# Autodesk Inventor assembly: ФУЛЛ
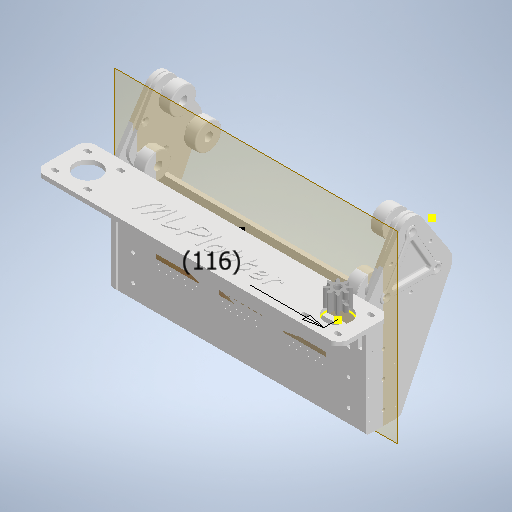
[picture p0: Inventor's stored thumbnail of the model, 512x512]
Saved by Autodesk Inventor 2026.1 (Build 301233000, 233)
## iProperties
Created: 2025-12
Part Number: ФУЛЛ
Document SubType Name: Assembly
Designer: Yury Melnikov
Author: Yury Melnikov
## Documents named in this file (8)
- C:\Users\user\Documents\Проекты\ВсОШ_РОБО\ФУЛЛ.iam
- C:\Users\user\Documents\Проекты\ВсОШ_РОБО\Стенд\СТЕНД.iam
- C:\Users\user\Documents\Проекты\ВсОШ_РОБО\Робот\Направляющие.ipt
- C:\Users\user\Documents\Проекты\ВсОШ_РОБО\Робот\Основная плита.ipt
- C:\Users\user\Documents\Проекты\ВсОШ_РОБО\Робот\Ребро жесткости.ipt
- C:\Users\user\Documents\Проекты\ВсОШ_РОБО\Робот\Направляющие_MIR1.ipt
- C:\Users\user\Documents\Проекты\ВсОШ_РОБО\Робот\Nema17H44.ipt
- C:\Users\user\Documents\Проекты\ВсОШ_РОБО\Робот\Шестеренки\Шестеренка.ipt
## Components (8 placed, 7 different names)
1. СТЕНД:1 [sub-assembly] — Совмещение:1, Касательность:1, Касательность:2, Заподлицо:1, Совмещение:2, Касательность:3, Касательность:4, Совмещение:13
2. Основная плита:1 — Совмещение:3, Совмещение:4, Совмещение:5, Совмещение:6, Совмещение:9, Совмещение:10, Совмещение:11
3. Ребро жесткости:1 — Совмещение:9, Совмещение:10, Совмещение:11
4. Направляющие:1 — Совмещение:1, Касательность:1, Касательность:2, Совмещение:5, Совмещение:6, Совмещение:14, Совмещение:15
5. Направляющие_MIR1:1 — Совмещение:2, Касательность:3, Касательность:4, Совмещение:3, Совмещение:4, Совмещение:7, Совмещение:8, Совмещение:12
6. Основная плита:2 — Совмещение:7, Совмещение:8, Совмещение:12
7. Nema17H44:1 — Совмещение:13, Совмещение:14, Совмещение:15, Совмещение:16
8. Шестеренка:1 — Совмещение:16
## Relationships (21: Mate 16, Tangent 4, Flush 1)
- Совмещение:1 [Mate]: СТЕНД:1 ↔ Направляющие:1
- Касательность:1 [Tangent]: СТЕНД:1 ↔ Направляющие:1
- Касательность:2 [Tangent]: СТЕНД:1 ↔ Направляющие:1
- Заподлицо:1 [Flush]: СТЕНД:1
- Совмещение:2 [Mate]: СТЕНД:1 ↔ Направляющие_MIR1:1
- Касательность:3 [Tangent]: СТЕНД:1 ↔ Направляющие_MIR1:1
- Касательность:4 [Tangent]: СТЕНД:1 ↔ Направляющие_MIR1:1
- Совмещение:3 [Mate]: Основная плита:1 ↔ Направляющие_MIR1:1
- Совмещение:4 [Mate]: Основная плита:1 ↔ Направляющие_MIR1:1
- Совмещение:5 [Mate]: Основная плита:1 ↔ Направляющие:1
- Совмещение:6 [Mate]: Основная плита:1 ↔ Направляющие:1
- Совмещение:7 [Mate]: Направляющие_MIR1:1 ↔ Основная плита:2
- Совмещение:8 [Mate]: Направляющие_MIR1:1 ↔ Основная плита:2
- Совмещение:9 [Mate]: Основная плита:1 ↔ Ребро жесткости:1
- Совмещение:10 [Mate]: Основная плита:1 ↔ Ребро жесткости:1
- Совмещение:11 [Mate]: Основная плита:1 ↔ Ребро жесткости:1
- Совмещение:12 [Mate]: Направляющие_MIR1:1 ↔ Основная плита:2
- Совмещение:13 [Mate]: СТЕНД:1 ↔ Nema17H44:1
- Совмещение:14 [Mate]: Направляющие:1 ↔ Nema17H44:1
- Совмещение:15 [Mate]: Направляющие:1 ↔ Nema17H44:1
- Совмещение:16 [Mate]: Nema17H44:1 ↔ Шестеренка:1
